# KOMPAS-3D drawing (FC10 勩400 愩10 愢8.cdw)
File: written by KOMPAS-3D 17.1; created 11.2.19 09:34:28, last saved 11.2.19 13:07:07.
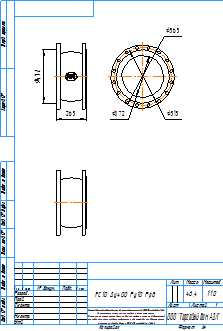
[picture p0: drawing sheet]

Sheet 1: A4, portrait

Title block, sheet 1: name: FC10 Ду400 Ру10 Рр8; mass: 46,4; sheets: 1; sheet format: A4; stored path: \\adlc.lan\data\АДЛ_ПКД\3D-модели\ADL production\Гибкие вставки серии FC\FC10\KOMPAS 2D\FC10 Ду400 Ру10 Рр8.cdw

Views: Вид 1
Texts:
  kka
  adl
  Рама для чертежей
  Лит-Масса-Масштаб
  Материал-Предприятие
  Масштаб
  Изм.
  Лист
  № докум.
  Подп.
  Дата
  Лит.
  Разраб.
  Пров.
  Т.контр.
  Листов
  Внимание! Данный продукт является объектом авторского права ООО «Торговый Дом АДЛ».
  Запрещается изменение, копирование, распространение
  (в том числе путем копирования на другие сайты и ресурсы в Интернете)
  или любое иное использование информации и объектов без предварительного
  согласия правообладателя (ООО «Торговый Дом АДЛ»).
  Н.контр.
  Утв.
  ООО "Торговый дом АДЛ"
  Изменение
  Номер документа
  Подпись
  Обозначение документа
  Наименование изделия
  Масса изделия по ГОСТ 2.109-73
  Порядковый номер листа
  Общее количество листов в документе
  Характер работы, выполненной лицом, подписавшим документ
  Наименование или индекс предприятия, выпускающего документ
  Инв. № подл.
  Подп. и дата
  Взам. инв. №
  Инв. № дубл.
  Инвентарный номер подлинника по ГОСТ 2.501-68
  Подпись принявшего подлинник в отдел технической документации
  Инвентарный номер подлинника, взамен которого выпущен данный подлинник
  Инвентарный номер дубликата по ГОСТ 2.502-68
  Подпись принявшего дубликат в отдел технической документации
  Справ. №
  Перв. примен.
  Обозначение документа, взамен или на основании которого выпущен данный документ
  Обозначение документа, в котором впервые записан данный документ
  Подпись лица, копировавшего чертеж
  Обозначение формата листа
  !Рама для чертежа
Dimensions and other numbers on the sheet: 265; 472; 372; 515; 565; 1:10; 1; 46,4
